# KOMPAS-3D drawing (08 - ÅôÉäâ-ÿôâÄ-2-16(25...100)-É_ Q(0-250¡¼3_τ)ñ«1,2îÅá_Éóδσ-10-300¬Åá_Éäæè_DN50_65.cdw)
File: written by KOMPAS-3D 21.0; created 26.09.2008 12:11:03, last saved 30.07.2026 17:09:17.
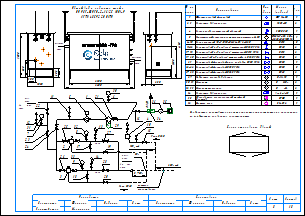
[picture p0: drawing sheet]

Sheets 1-2: A3, landscape

Document properties: Наименование: Макро:21; Автор: RaskoAdmin; Форматы листов документа: 2xA3; Полное имя файла: \\ur38nt01\Departments\КТО\КБ ПУРДГ\Заявки\Прайс-лист на типовые шкафы ГРПШ\ПУРДГ_стандарт_30_04_2026\ПУРДГ с РДСК\ПУРДГ-ШУГО-2-16(25...100)-Р_ Q(0-250нм3_ч)до1,2МПа_Рвых-10-300кПа_РДСК_DN50_65.cdw

Title block, sheet 1: Наименование: Пункт учета газа / ПУГ-Ш-400-Р / ЛГТИ.485922.001ТУ; designation: ЛГТИ.03.4411141; sheet number: 1; Количество листов документа: 2; organisation: ООО "ЭЛЬСТЕР Газэлектроника"; Форматы листов документа: A3; stored path: C:\Рабочие документы\Компас\ПУГ\Схема.cdw; Разработал: Устинов; Проверил: Кошкин; Утвердил: Кошкин
Title block, sheet 2: sheet number: 2; stored path: D:\Рабочие документы\Заявки\ПУРДГ\ПУРДГ-ШУЭО-2-100-Р 4411220.cdw; designation, second copy: ЛГТИ.03.4411141-

Views: Вид 1, Вид 2
Referenced files: wcvoit.frw
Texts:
  Normal
  № на
  схеме
  Усл.
  обозн.
  Марка
  (модель)
  Кол.
  Фильтр газовый фланцевый
  ФГ 16-50
  Регулятор давления газа
  РДСК-50
  Клапан предохранительный сбросной
  КПС DN20
  Измерительный комплекс с ротационным счетчиком Ду50
  СГ-ЭК-Р-(0,2...2,0)-
  Кран кнопочный VE-РАСКО-НЗ-1,6-G1/2-М20
  DN15
  Кран шаровой "под приварку" штуцерный DN20 PN16
  DN20
  Кран шаровой "под приварку" штуцерный DN15 PN16
  Кран шаровой "под приварку" штуцерный п/п DN20 PN16
  Кран шаровой фланцевый с мех. приводом DN50 PN16
  Кран шаровой фланцевый DN50 PN16
  Кран шаровой фланцевый DN65 PN16
  DN50
  DN65
  Индикатор перепада давления
  Манометр
  Манометр-напоромер
  Обогреватель газогорелочный шкафной
  (Эльтон")
  Счетчик газа
  Delta 15
  0...     МПа
  0...     кПа
  Venio-A-15
  ОГШН
  BK-G1,6
  Общий вид и габариты шкафа
  ПУРДГ-ШУГО-2-16(25...100)-Р
  Выход газа
  Вход газа
  logo-rasko-ge.png
  DN 1
  местное
  сопротивление
  Римп DN20
  Выход
  газа
  Р=     кПа
  Вход
  Р=       МПа
  PDI
  Схема открывания дверей
  Предприятие изготовитель может заменять комплектующие на аналогичные,
  не ухудшающие заявленных характеристик.
  Должность
  Конструктор
  Фамилия
  Подпись
  Дата
  Согласовано
  Максимкин
  Лист
  Листов
  POLYLINE_STYLE_0.18_RGB_0_0_0
  POLYLINE_STYLE_0.50_RGB_0_0_0
  POLYLINE_STYLE_0.34_RGB_0_0_0
  PHANTOM_RGB_0_0_0_SC_1_THICK_0.18
  K5LT_THIN_RGB_0_0_0_THICK_0.18
  K5LT32769_RGB_0_0_0_THICK_0.18
  K5LT12_RGB_0_0_0_SC_1_THICK_0.18
  K5LT_DASHED_RGB_0_0_0_SC_1_THICK_0.18
  ACISOTGL_RGB_0_0_0_SC_0.8_THICK_0.25
  CONTINUOUS_RGB_0_127_31_THICK_0.3
  CONTINUOUS_RGB_0_0_255_THICK_0.35
  CONTINUOUS_RGB_255_0_0_THICK_0.35
  POLYLINE_STYLE_0.25_RGB_0_0_0
  CONTINUOUS_RGB_0_0_0_THICK_0.5
  POLYLINE_STYLE_0.35_RGB_0_0_255
  CONTINUOUS_RGB_0_0_0_THICK_0.4
  CONTINUOUS_RGB_0_0_0_THICK_0.35
  НЕВИДИМАЯ_RGB_0_0_0_SC_0.3_THICK_0.25
  СONTINUOUS_RGB_0_0_0_THICK_0.25
  ОСЕВАЯ2_RGB_248_153_30_SC_0.3_THICK_0.25
  Без оформления
Dimensions and other numbers on the sheet: 1; 2, 3; 2; 4; 5; 6-10; 11-16; 6; 17, 18; 19, 20; 21; 22-26; 27, 28; 29; 30, 31; 32, 33; 34; 35; 36; 1500; 250; 300; 1050; 550; 305; 2300; 4130; 2000; 2600; 5,,,7DN 1; 7; 31; 12; 22; 23; 24; 11; 30; 25; 32; 8; 17; 13; 27; 19; 10; 15; 26; 33; 9; 3; 18; 14; 28; 20; 16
